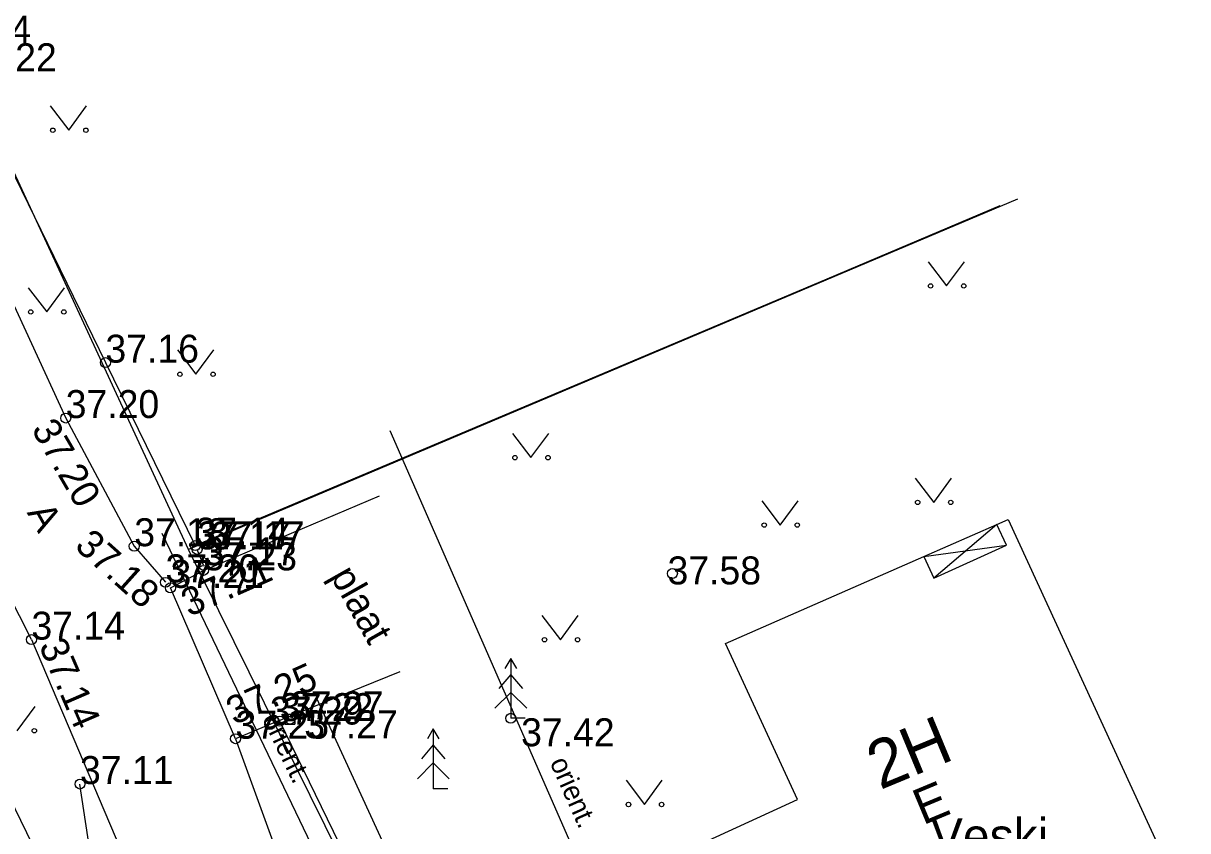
# Model space of a CAD drawing. Extents: x 627548 to 628052, y 6467984 to 6468802.
# Drawn here: x 627663.96 to 627693.12, y 6468367.55 to 6468387.78 of the extents above; entities that cross this region are included whole.
import ezdxf

# ---------------------------------------------------------------- set-up
doc = ezdxf.new("R2010")
doc.units = 0
for name, color, linetype in [('AED', 7, 'Continuous'), ('HALJASTUS', 7, 'Continuous'), ('HOONE', 7, 'Continuous'), ('HOONEDET', 7, 'Continuous'), ('KORGUS-EH2000', 7, 'Continuous'), ('KTRASS', 7, 'Continuous'), ('MOOTKORG-EH2000', 7, 'Continuous'), ('MOOTMPUNKT', 7, 'Continuous'), ('PIIR', 7, 'Continuous'), ('PUU', 7, 'Continuous'), ('SKTRASS', 7, 'Continuous'), ('TEE', 7, 'Continuous'), ('VTRASS', 7, 'Continuous')]:
    doc.layers.add(name, color=color, linetype=linetype)

msp = doc.modelspace()

# ---------------------------------------------------------------- linework, layer by layer
at = {"layer": 'AED'}
for p, q in [((627668.474, 6468374.202), (627668.311, 6468374.599)), ((627670.514, 6468370.47), (627670.514, 6468370.22)), ((627670.514, 6468370.47), (627670.764, 6468370.47)), ((627670.764, 6468370.47), (627670.764, 6468370.22)), ((627670.514, 6468370.22), (627670.764, 6468370.22))]:
    msp.add_line(p, q, dxfattribs=at)
for points in [[(627662.455, 6468386.577), (627666.016, 6468379.277), (627668.267, 6468374.693)], [(627668.267, 6468374.693), (627684.095, 6468381.374), (627688.427, 6468383.213)], [(627676.876, 6468356.909), (627673.668, 6468363.549), (627670.384, 6468370.298)]]:
    msp.add_lwpolyline(points, dxfattribs=at)
at = {"layer": 'HALJASTUS'}
for p, q in [((627664.635, 6468385.707), (627665.099, 6468385.1)), ((627665.099, 6468385.1), (627665.544, 6468385.707)), ((627686.622, 6468381.805), (627687.085, 6468381.198)), ((627687.085, 6468381.198), (627687.531, 6468381.805)), ((627664.083, 6468381.155), (627664.546, 6468380.548)), ((627664.546, 6468380.548), (627664.992, 6468381.155)), ((627667.82, 6468379.594), (627668.283, 6468378.987)), ((627668.283, 6468378.987), (627668.729, 6468379.594)), ((627676.21, 6468377.504), (627676.674, 6468376.897)), ((627676.674, 6468376.897), (627677.119, 6468377.504)), ((627686.298, 6468376.382), (627686.761, 6468375.776)), ((627686.761, 6468375.776), (627687.207, 6468376.382)), ((627682.454, 6468375.816), (627682.917, 6468375.209)), ((627682.917, 6468375.209), (627683.363, 6468375.816)), ((627676.95, 6468372.943), (627677.414, 6468372.336)), ((627677.414, 6468372.336), (627677.859, 6468372.943)), ((627663.807, 6468370.057), (627664.253, 6468370.664)), ((627679.055, 6468368.815), (627679.518, 6468368.209)), ((627679.518, 6468368.209), (627679.963, 6468368.815))]:
    msp.add_line(p, q, dxfattribs=at)
msp.add_lwpolyline([(627677.3, 6468357.854), (627671.313, 6468370.862)], dxfattribs=at)
for centre in [(627664.698, 6468385.1), (627665.526, 6468385.1), (627686.684, 6468381.198), (627687.513, 6468381.198), (627664.145, 6468380.548), (627664.974, 6468380.548), (627667.882, 6468378.987), (627668.711, 6468378.987), (627676.273, 6468376.897), (627677.101, 6468376.897), (627686.36, 6468375.776), (627687.189, 6468375.776), (627682.516, 6468375.209), (627683.345, 6468375.209), (627677.013, 6468372.336), (627677.841, 6468372.336), (627664.235, 6468370.057), (627679.117, 6468368.209), (627679.946, 6468368.209)]:
    msp.add_circle(centre, 0.055, dxfattribs=at)
at = {"layer": 'HOONE'}
for points in [[(627683.344, 6468361.058), (627680.604, 6468367.07), (627683.347, 6468368.337), (627681.543, 6468372.245), (627686.517, 6468374.421), (627686.768, 6468373.881), (627688.585, 6468374.705), (627688.345, 6468375.224), (627688.627, 6468375.344), (627693.124, 6468365.572), (627683.344, 6468361.058)], [(627686.517, 6468374.421), (627688.345, 6468375.224)]]:
    msp.add_lwpolyline(points, dxfattribs=at)
at = {"layer": 'HOONEDET'}
for points in [[(627688.345, 6468375.224), (627686.768, 6468373.881)], [(627686.517, 6468374.421), (627688.585, 6468374.705)]]:
    msp.add_lwpolyline(points, dxfattribs=at)
at = {"layer": 'KORGUS-EH2000'}
for centre in [(627680.216, 6468373.994), (627676.168, 6468370.368)]:
    msp.add_circle(centre, 0.125, dxfattribs=at)
at = {"layer": 'KTRASS'}
msp.add_lwpolyline([(627669.837, 6468355.594), (627653.907, 6468388.368), (627661.842, 6468392.243)], dxfattribs=at)
at = {"layer": 'MOOTMPUNKT'}
for centre in [(627666.016, 6468379.277), (627665.021, 6468377.889), (627666.738, 6468374.679), (627668.267, 6468374.693), (627668.311, 6468374.599), (627668.471, 6468374.074), (627668.474, 6468374.202), (627667.521, 6468373.774), (627667.645, 6468373.635), (627664.163, 6468372.339), (627670.384, 6468370.298), (627670.639, 6468370.345), (627670.134, 6468370.211), (627669.275, 6468369.857), (627665.379, 6468368.721)]:
    msp.add_circle(centre, 0.125, dxfattribs=at)
at = {"layer": 'PIIR'}
for p, q in [((627668.1, 6468374.6), (627655.45, 6468401.9)), ((627688.862, 6468383.373), (627668.1, 6468374.6)), ((627685.55, 6468339.27), (627668.1, 6468374.6))]:
    msp.add_line(p, q, dxfattribs=at)
at = {"layer": 'PUU'}
for p, q in [((627676.168, 6468371.868), (627676.018, 6468371.618)), ((627676.318, 6468371.618), (627676.168, 6468371.868)), ((627676.168, 6468371.868), (627676.168, 6468370.368)), ((627676.168, 6468371.468), (627675.868, 6468371.118)), ((627676.468, 6468371.118), (627676.168, 6468371.468)), ((627676.168, 6468371.018), (627675.768, 6468370.618)), ((627676.568, 6468370.618), (627676.168, 6468371.018)), ((627674.229, 6468370.102), (627674.079, 6468369.852)), ((627674.379, 6468369.852), (627674.229, 6468370.102)), ((627674.229, 6468370.102), (627674.229, 6468368.602)), ((627676.528, 6468370.368), (627676.168, 6468370.368)), ((627674.229, 6468369.702), (627673.929, 6468369.352)), ((627674.529, 6468369.352), (627674.229, 6468369.702)), ((627674.229, 6468369.252), (627673.829, 6468368.852)), ((627674.629, 6468368.852), (627674.229, 6468369.252)), ((627674.589, 6468368.602), (627674.229, 6468368.602))]:
    msp.add_line(p, q, dxfattribs=at)
at = {"layer": 'SKTRASS'}
msp.add_lwpolyline([(627681.712, 6468358.005), (627673.151, 6468377.568)], dxfattribs=at)
at = {"layer": 'TEE'}
for points in [[(627664.163, 6468372.339), (627656.73, 6468386.978), (627654.281, 6468392.2), (627651.487, 6468398.488), (627650.055, 6468402.405), (627646.281, 6468409.175), (627642.033, 6468417.224), (627639.524, 6468421.265)], [(627661.81, 6468387.273), (627661.432, 6468386.438), (627661.576, 6468385.372), (627665.021, 6468377.889), (627666.738, 6468374.679), (627667.521, 6468373.774)], [(627673.391, 6468371.529), (627670.134, 6468370.211), (627669.275, 6468369.857), (627667.645, 6468373.635), (627668.471, 6468374.074), (627672.881, 6468375.942)], [(627664.163, 6468372.339), (627666.781, 6468366.19), (627672.084, 6468355.605)], [(627669.275, 6468369.857), (627670.241, 6468367.186), (627674.912, 6468357.546), (627676.157, 6468356.482)], [(627664.511, 6468357.839), (627665.439, 6468360.645), (627665.995, 6468363.347), (627665.915, 6468365.146), (627665.379, 6468368.721)]]:
    msp.add_lwpolyline(points, dxfattribs=at)
at = {"layer": 'VTRASS'}
msp.add_lwpolyline([(627673.444, 6468362.479), (627667.441, 6468375)], dxfattribs=at)

# ---------------------------------------------------------------- texts
at = {"layer": 'HOONE'}
for s, height, rotation, p in [('2H', 1.2, 22.5098, (627685.419, 6468368.568)), ('E', 0.9, 22.6199, (627686.492, 6468367.684))]:
    msp.add_text(s, height=height, rotation=rotation, dxfattribs=at).set_placement(p)
at = {"layer": 'KORGUS-EH2000'}
for s, rotation, p in [('37.20', 300.2501, (627664.148, 6468377.609)), ('37.18', 318.1147, (627665.217, 6468374.644)), ('37.21', 23.8935, (627668.115, 6468372.903)), ('37.14', 293.4534, (627664.341, 6468372.19)), ('37.25', 24.0265, (627669.245, 6468370.193))]:
    msp.add_text(s, height=0.7, rotation=rotation, dxfattribs=at).set_placement(p)
for s, p in [('37.17', (627668.661, 6468374.599)), (' 37.58 ', (627679.834, 6468373.722)), ('37.27', (627670.995, 6468369.868)), (' 37.42 ', (627676.168, 6468369.668))]:
    msp.add_text(s, height=0.7, dxfattribs=at).set_placement(p)
at = {"layer": 'MOOTKORG-EH2000'}
for s, p in [('37.24', (627661.81, 6468387.273)), ('37.22', (627662.455, 6468386.577)), ('37.16', (627666.016, 6468379.277)), ('37.20', (627665.021, 6468377.889)), ('37.18', (627666.738, 6468374.679)), ('37.14', (627668.267, 6468374.693)), ('37.17', (627668.311, 6468374.599)), ('37.23', (627668.471, 6468374.074)), ('37.17', (627668.474, 6468374.202)), ('37.20', (627667.521, 6468373.774)), ('37.21', (627667.645, 6468373.635)), ('37.14', (627664.163, 6468372.339)), ('37.22', (627670.384, 6468370.298)), ('37.27', (627670.639, 6468370.345)), ('37.29', (627670.134, 6468370.211)), ('37.25', (627669.275, 6468369.857)), ('37.11', (627665.379, 6468368.721))]:
    msp.add_text(s, height=0.7, dxfattribs=at).set_placement(p)
at = {"layer": 'PIIR'}
msp.add_text('Veski', height=0.9, dxfattribs=at).set_placement((627686.69, 6468366.966))
at = {"layer": 'SKTRASS'}
msp.add_text('orient.', height=0.5, rotation=293.973, dxfattribs=at).set_placement((627677.138, 6468369.266))
at = {"layer": 'TEE'}
for s, p in [('A', (627664.039, 6468375.52)), ('plaat', (627671.629, 6468373.938))]:
    msp.add_text(s, height=0.7, rotation=299.4537, dxfattribs=at).set_placement(p)
at = {"layer": 'VTRASS'}
msp.add_text('orient.', height=0.5, rotation=295.6475, dxfattribs=at).set_placement((627669.933, 6468370.365))

doc.saveas('drawing.dxf')
